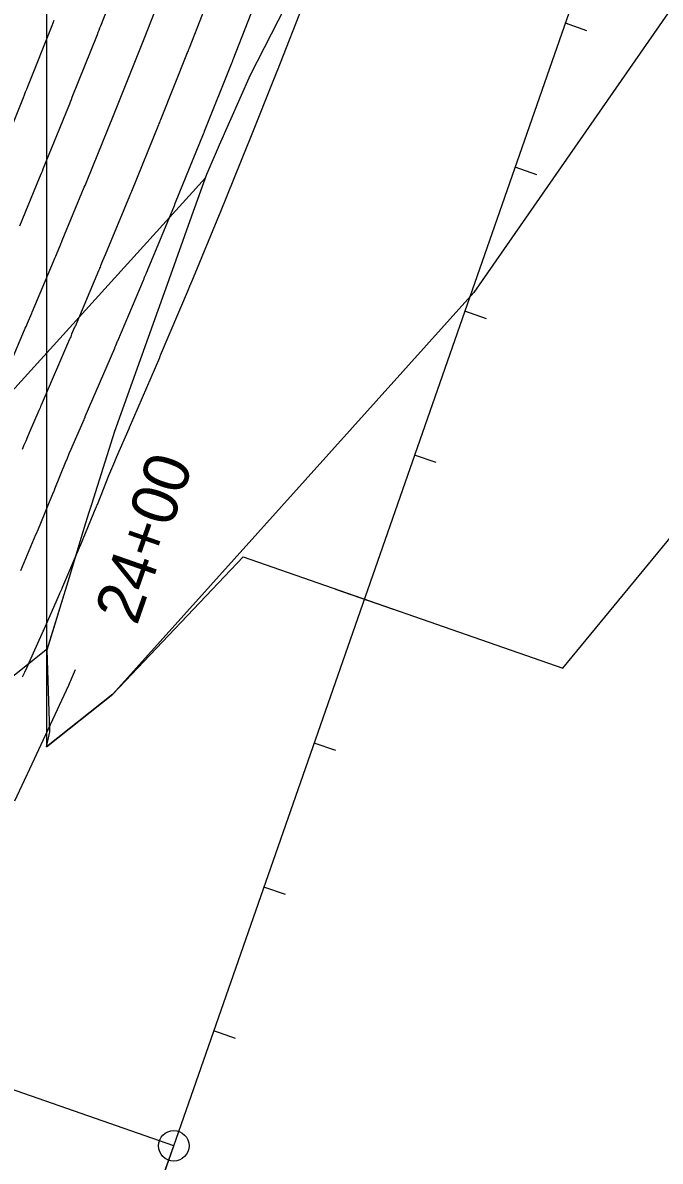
# Model space of a CAD drawing. Extents: x 1710723 to 1713003, y 548603 to 551142.
# Drawn here: x 1712358.5 to 1712442.1, y 549508.2 to 549657.6 of the extents above; entities that cross this region are included whole.
import ezdxf

# ---------------------------------------------------------------- set-up
doc = ezdxf.new("R2010")
doc.units = 0
for name, color, linetype in [('R_Contours', 7, 'Continuous'), ('R_Horz Alg', 7, 'Continuous'), ('R_Horz Alg Annot', 7, 'Continuous'), ('R_MOT', 7, 'Continuous'), ('R_No Plot', 7, 'Continuous')]:
    doc.layers.add(name, color=color, linetype=linetype)

msp = doc.modelspace()

# ---------------------------------------------------------------- linework, layer by layer
at = {"layer": 'R_Contours'}
for points in [[(1712371.93, 549665.4), (1712368.69, 549657.12), (1712368.57, 549656.84), (1712368.46, 549656.55), (1712368.35, 549656.27), (1712368.24, 549655.99), (1712364.94, 549647.73), (1712364.83, 549647.44), (1712364.71, 549647.15), (1712364.6, 549646.86), (1712364.48, 549646.57), (1712361.14, 549638.35), (1712361.02, 549638.05), (1712360.9, 549637.76), (1712360.78, 549637.47), (1712360.66, 549637.18), (1712358.04, 549630.86)], [(1712355.11, 549608.84), (1712358.73, 549617.26), (1712358.82, 549617.48), (1712358.92, 549617.7), (1712359.01, 549617.92), (1712359.11, 549618.15), (1712359.66, 549619.46), (1712359.68, 549619.51), (1712359.71, 549619.58), (1712359.72, 549619.6), (1712362.52, 549626.23), (1712362.62, 549626.46), (1712362.71, 549626.69), (1712362.81, 549626.92), (1712362.9, 549627.15), (1712363.44, 549628.44), (1712363.46, 549628.49), (1712363.48, 549628.53), (1712363.5, 549628.58), (1712363.51, 549628.63), (1712363.59, 549628.81), (1712363.61, 549628.86), (1712363.63, 549628.9), (1712363.65, 549628.95), (1712363.67, 549628.99), (1712366.56, 549635.98), (1712366.66, 549636.21), (1712366.75, 549636.43), (1712366.84, 549636.66), (1712366.93, 549636.88), (1712370.39, 549645.38), (1712370.48, 549645.6), (1712370.57, 549645.82), (1712370.65, 549646.04), (1712370.74, 549646.26), (1712374.14, 549654.79), (1712374.23, 549655.01), (1712374.32, 549655.22), (1712374.4, 549655.44), (1712374.49, 549655.66), (1712377.83, 549664.2)], [(1712383.73, 549663), (1712380.29, 549654.2), (1712380.23, 549654.05), (1712380.17, 549653.89), (1712380.11, 549653.74), (1712380.05, 549653.59), (1712376.54, 549644.8), (1712376.48, 549644.65), (1712376.42, 549644.49), (1712376.35, 549644.34), (1712376.29, 549644.18), (1712372.73, 549635.42), (1712372.67, 549635.26), (1712372.6, 549635.1), (1712372.54, 549634.94), (1712372.47, 549634.79), (1712369.3, 549627.13), (1712369.28, 549627.08), (1712369.26, 549627.03), (1712369.24, 549626.98), (1712369.22, 549626.93), (1712369.13, 549626.73), (1712369.11, 549626.68), (1712369.09, 549626.63), (1712369.07, 549626.58), (1712369.05, 549626.54), (1712368.69, 549625.66), (1712368.62, 549625.5), (1712368.55, 549625.34), (1712368.49, 549625.17), (1712368.42, 549625.01), (1712365.34, 549617.71), (1712365.32, 549617.68), (1712365.3, 549617.62), (1712365.29, 549617.62), (1712364.9, 549616.69), (1712364.84, 549616.53), (1712364.77, 549616.37), (1712364.7, 549616.22), (1712364.63, 549616.06), (1712360.9, 549607.37), (1712360.83, 549607.2), (1712360.75, 549607.03), (1712360.68, 549606.86), (1712360.61, 549606.69), (1712359.33, 549603.77), (1712359.1, 549603.23), (1712358.87, 549602.68), (1712358.64, 549602.13), (1712358.42, 549601.58)], [(1712358.22, 549585.72), (1712360.21, 549590.41), (1712360.22, 549590.42), (1712360.36, 549590.74), (1712360.38, 549590.79), (1712360.4, 549590.85), (1712360.42, 549590.9), (1712360.45, 549590.95), (1712362.4, 549595.66), (1712362.41, 549595.69), (1712362.42, 549595.72), (1712362.45, 549595.78), (1712362.45, 549595.79), (1712362.46, 549595.81), (1712362.47, 549595.82), (1712362.47, 549595.84), (1712362.61, 549596.16), (1712362.64, 549596.22), (1712362.66, 549596.28), (1712362.69, 549596.34), (1712362.71, 549596.4), (1712364.1, 549599.86), (1712364.34, 549600.45), (1712364.59, 549601.04), (1712364.83, 549601.62), (1712365.08, 549602.21), (1712366.52, 549605.5), (1712366.56, 549605.6), (1712366.61, 549605.7), (1712366.65, 549605.8), (1712366.69, 549605.9), (1712370.54, 549614.86), (1712370.58, 549614.95), (1712370.62, 549615.04), (1712370.66, 549615.14), (1712370.7, 549615.23), (1712370.93, 549615.77), (1712370.95, 549615.82), (1712374.31, 549623.79), (1712374.35, 549623.89), (1712374.39, 549623.98), (1712374.43, 549624.07), (1712374.47, 549624.17), (1712374.66, 549624.63), (1712374.68, 549624.68), (1712374.71, 549624.73), (1712374.73, 549624.79), (1712374.75, 549624.84), (1712374.84, 549625.05), (1712374.86, 549625.1), (1712374.88, 549625.16), (1712374.9, 549625.21), (1712374.93, 549625.26), (1712378.38, 549633.59), (1712378.41, 549633.68), (1712378.45, 549633.77), (1712378.49, 549633.87), (1712378.53, 549633.96), (1712382.2, 549642.98), (1712382.23, 549643.07), (1712382.27, 549643.16), (1712382.3, 549643.25), (1712382.34, 549643.34), (1712385.95, 549652.39), (1712385.98, 549652.48), (1712386.02, 549652.57), (1712386.05, 549652.65), (1712386.09, 549652.74), (1712389.63, 549661.81)], [(1712358.47, 549571.74), (1712358.76, 549572.38), (1712359.05, 549573.02), (1712359.34, 549573.65), (1712361.03, 549577.45), (1712361.04, 549577.47), (1712361.05, 549577.49), (1712361.06, 549577.51), (1712361.07, 549577.53), (1712361.13, 549577.64), (1712361.14, 549577.67), (1712361.16, 549577.72), (1712361.17, 549577.73), (1712361.24, 549577.89), (1712361.26, 549577.91), (1712361.27, 549577.94), (1712361.28, 549577.97), (1712361.3, 549578), (1712363.18, 549582.31), (1712363.18, 549582.32), (1712363.19, 549582.34), (1712363.2, 549582.36), (1712363.21, 549582.38), (1712363.26, 549582.5), (1712363.28, 549582.53), (1712363.34, 549582.65), (1712363.35, 549582.67), (1712363.36, 549582.7), (1712363.37, 549582.72), (1712363.37, 549582.74), (1712363.64, 549583.36), (1712363.65, 549583.38), (1712363.66, 549583.4), (1712363.67, 549583.42), (1712363.68, 549583.44), (1712363.72, 549583.53), (1712363.73, 549583.55), (1712363.73, 549583.57), (1712363.74, 549583.59), (1712363.75, 549583.61), (1712365.92, 549588.7), (1712365.92, 549588.7), (1712365.97, 549588.82), (1712365.98, 549588.84), (1712365.99, 549588.86), (1712365.99, 549588.88), (1712366, 549588.9), (1712368.12, 549594), (1712368.13, 549594.03), (1712368.14, 549594.06), (1712368.17, 549594.12), (1712368.17, 549594.14), (1712368.18, 549594.16), (1712368.19, 549594.17), (1712368.19, 549594.19), (1712368.23, 549594.28), (1712368.24, 549594.3), (1712368.25, 549594.32), (1712368.26, 549594.34), (1712368.27, 549594.36), (1712369.79, 549598.15), (1712370.04, 549598.77), (1712370.3, 549599.4), (1712370.57, 549600.02), (1712370.83, 549600.65), (1712372.43, 549604.31), (1712372.44, 549604.34), (1712372.46, 549604.37), (1712372.47, 549604.4), (1712372.49, 549604.44), (1712376.45, 549613.66), (1712376.46, 549613.69), (1712376.47, 549613.71), (1712376.48, 549613.74), (1712376.5, 549613.77), (1712376.56, 549613.93), (1712376.57, 549613.94), (1712380.21, 549622.57), (1712380.22, 549622.6), (1712380.23, 549622.62), (1712380.25, 549622.65), (1712380.26, 549622.68), (1712380.3, 549622.78), (1712380.32, 549622.83), (1712380.34, 549622.89), (1712380.46, 549623.17), (1712380.49, 549623.23), (1712380.51, 549623.28), (1712380.53, 549623.34), (1712380.56, 549623.39), (1712384.28, 549632.4), (1712384.29, 549632.42), (1712384.3, 549632.45), (1712384.31, 549632.47), (1712384.32, 549632.5), (1712388.1, 549641.79), (1712388.11, 549641.81), (1712388.12, 549641.83), (1712388.13, 549641.86), (1712388.14, 549641.88), (1712391.85, 549651.19), (1712391.87, 549651.24), (1712391.89, 549651.28), (1712395.54, 549660.61)], [(1712355.34, 549639.81), (1712358.57, 549647.77), (1712358.72, 549648.12), (1712358.86, 549648.48), (1712359, 549648.83), (1712359.15, 549649.19), (1712362.33, 549657.18), (1712362.47, 549657.53), (1712362.61, 549657.88)], [(1712357.43, 549555.51), (1712358.71, 549558.18), (1712358.72, 549558.2), (1712358.73, 549558.22), (1712358.73, 549558.24), (1712358.74, 549558.25), (1712358.78, 549558.32), (1712358.79, 549558.34), (1712358.79, 549558.36), (1712358.8, 549558.37), (1712358.81, 549558.39), (1712364.51, 549570.67), (1712364.6, 549570.87), (1712364.69, 549571.08), (1712364.78, 549571.28), (1712364.88, 549571.48), (1712365.42, 549572.71)]]:
    msp.add_lwpolyline(points, dxfattribs=at)
at = {"layer": 'R_Horz Alg'}
msp.add_line((1712378.29, 549510.24), (1712448.88, 549712.66), dxfattribs=at)
msp.add_arc((1711777.17, 549719.88), 636.62, 271.07865, 340.7734, dxfattribs=at)
at = {"layer": 'R_Horz Alg Annot'}
msp.add_line((1712232.32, 549091.72), (1712378.29, 549510.24), dxfattribs=at)
for points in [[(1712432.47, 549656.5), (1712429.64, 549657.49)], [(1712425.89, 549637.62), (1712423.05, 549638.6)], [(1712419.3, 549618.73), (1712416.47, 549619.72)], [(1712412.71, 549599.85), (1712409.88, 549600.84)], [(1712399.52, 549583.27), (1712407.07, 549580.63)], [(1712399.54, 549562.08), (1712396.71, 549563.07)], [(1712378.29, 549510.24), (1712264.98, 549549.75)], [(1712392.96, 549543.19), (1712390.12, 549544.18)], [(1712386.37, 549524.31), (1712383.54, 549525.3)]]:
    msp.add_lwpolyline(points, dxfattribs=at)
msp.add_circle((1712378.29, 549510.24), 2, dxfattribs=at)
at = {"layer": 'R_MOT'}
for points in [[(1712478.07, 549727.7), (1712475.64, 549720.74), (1712469.03, 549704.48), (1712444.83, 549661.33), (1712417.63, 549622.18), (1712370.31, 549569.49), (1712361.6, 549562.59)], [(1712361.6, 549562.59), (1712362.05, 549564.56), (1712361.69, 549575.28), (1712364.61, 549584.85), (1712364.95, 549585.99), (1712366.6, 549591.38), (1712367.17, 549593.22), (1712367.49, 549594.26), (1712367.54, 549594.42), (1712370.56, 549603.96), (1712373.94, 549613.37), (1712377.28, 549622.8), (1712377.67, 549623.88), (1712380.64, 549632.22), (1712382.61, 549637.69), (1712382.79, 549638.08), (1712384.29, 549641.53), (1712388.35, 549650.71), (1712392.93, 549659.7)], [(1712382.44, 549637.22), (1712376.86, 549631.06), (1712365.88, 549618.95), (1712354.89, 549606.84), (1712343.9, 549594.73), (1712324.74, 549579.52), (1712305.58, 549564.31), (1712293.62, 549556.65), (1712281.65, 549548.99), (1712265.07, 549541.04), (1712248.48, 549533.1), (1712232.1, 549528.44), (1712215.71, 549523.78), (1712191.89, 549519.6), (1712168.07, 549515.43), (1712151.97, 549514.41), (1712135.87, 549513.4), (1712119.76, 549512.39)], [(1712361.75, 549575.47), (1712364.61, 549584.85), (1712364.95, 549585.99), (1712366.6, 549591.38), (1712367.17, 549593.22), (1712367.49, 549594.26), (1712367.54, 549594.42), (1712370.56, 549603.96), (1712373.94, 549613.37), (1712377.28, 549622.8), (1712377.67, 549623.88), (1712380.64, 549632.22), (1712382.44, 549637.22)], [(1712242.17, 549505.09), (1712260.77, 549511.2), (1712278.61, 549519.22), (1712296.46, 549527.24), (1712308.7, 549535.18), (1712320.94, 549543.12), (1712331.56, 549551.54), (1712342.19, 549559.96), (1712352.81, 549568.38), (1712361.75, 549575.47)]]:
    msp.add_lwpolyline(points, dxfattribs=at)
at = {"layer": 'R_No Plot'}
msp.add_line((1712429.32, 549572.87), (1712471.46, 549624.18), dxfattribs=at)
for points in [[(1712635.83, 549942.65), (1712361.6, 549942.65), (1712361.6, 549562.59)], [(1712361.6, 549562.59), (1712370.31, 549569.49), (1712387.41, 549587.49), (1712429.32, 549572.87)]]:
    msp.add_lwpolyline(points, dxfattribs=at)

# ---------------------------------------------------------------- texts
at = {"layer": 'R_Horz Alg Annot'}
msp.add_text('24+00', height=6, rotation=70.7734, dxfattribs=at).set_placement((1712373.45, 549578.37))

doc.saveas('drawing.dxf')
